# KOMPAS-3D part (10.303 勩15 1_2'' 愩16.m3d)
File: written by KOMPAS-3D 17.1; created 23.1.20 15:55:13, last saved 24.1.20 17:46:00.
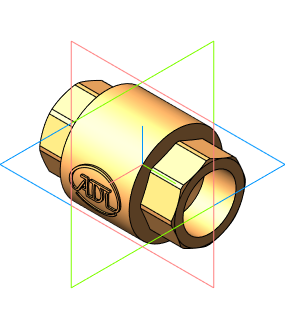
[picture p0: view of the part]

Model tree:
1. Операция без истории:2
